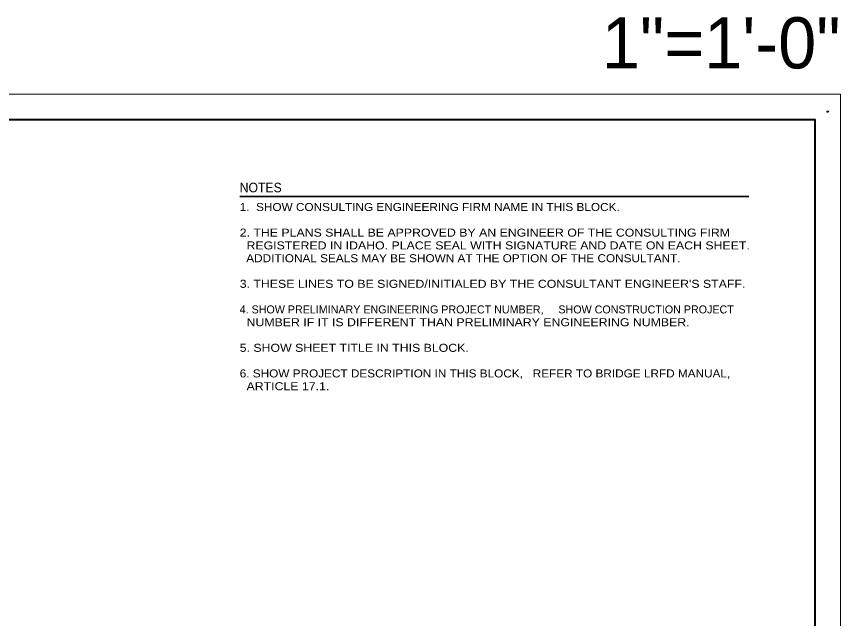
# Model space of a CAD drawing. Extents: x 0 to 34, y 0 to 23.5.
# Drawn here: x 17.91 to 34, y 11.76 to 23.51 of the extents above; entities that cross this region are included whole.
import ezdxf
from ezdxf.enums import TextEntityAlignment as Align

# ---------------------------------------------------------------- set-up
doc = ezdxf.new("R2010")
doc.units = 0
doc.header["$LTSCALE"] = 0.05
doc.header["$PDMODE"] = 32
doc.header["$PDSIZE"] = 0.025
doc.layers.add('49', color=7, linetype='Continuous')
doc.layers.add('50', color=7, linetype='Continuous', lineweight=13)
doc.layers.add('54', color=7, linetype='Continuous', lineweight=25)

msp = doc.modelspace()

# ---------------------------------------------------------------- linework, layer by layer
at = {"layer": '49'}
msp.add_point((33.75, 21.65625), dxfattribs=at)
at = {"layer": '50'}
msp.add_lwpolyline([(0, 22), (34, 22), (34, 0), (0, 0)], close=True, dxfattribs=at)
at = {"layer": '50', "lineweight": 40}
msp.add_lwpolyline([(1.5, 21.5), (33.5, 21.5), (33.5, 0.5), (1.5, 0.5)], close=True, dxfattribs=at)
at = {"layer": '54', "lineweight": 35}
msp.add_line((22.26536, 19.99708), (32.20615, 19.99708), dxfattribs=at)

# ---------------------------------------------------------------- texts
at = {"layer": '50'}
msp.add_text('1"=1\'-0"', height=1, dxfattribs=at).set_placement((34.00068, 22.5), align=Align.RIGHT)
at = {"layer": '54'}
for s, height, width, p in [('NOTES', 0.1875, 0.95, (22.26536, 20.08042)), ('1.  SHOW CONSULTING ENGINEERING FIRM NAME IN THIS BLOCK.', 0.1563, 1.1, (22.26536, 19.71583)), ('2. THE PLANS SHALL BE APPROVED BY AN ENGINEER OF THE CONSULTING FIRM', 0.1563, 1.15, (22.26536, 19.21583)), ('  REGISTERED IN IDAHO. PLACE SEAL WITH SIGNATURE AND DATE ON EACH SHEET.', 0.1563, 1.15, (22.26536, 18.96583)), ('  ADDITIONAL SEALS MAY BE SHOWN AT THE OPTION OF THE CONSULTANT.', 0.1563, 1.1, (22.26536, 18.71583)), ("3. THESE LINES TO BE SIGNED/INITIALED BY THE CONSULTANT ENGINEER'S STAFF.", 0.1563, 1.15, (22.26536, 18.21583)), ('  NUMBER IF IT IS DIFFERENT THAN PRELIMINARY ENGINEERING NUMBER.', 0.1563, 1.15, (22.26536, 17.46583)), ('5. SHOW SHEET TITLE IN THIS BLOCK.', 0.1563, 1.15, (22.26536, 16.96583)), ('6. SHOW PROJECT DESCRIPTION IN THIS BLOCK,   REFER TO BRIDGE LRFD MANUAL,', 0.1563, 1.1, (22.26536, 16.46583)), ('  ARTICLE 17.1.', 0.1563, 1.15, (22.26536, 16.21583))]:
    msp.add_text(s, height=height, dxfattribs=dict(at, width=width)).set_placement(p)
msp.add_text('4. SHOW PRELIMINARY ENGINEERING PROJECT NUMBER,     SHOW CONSTRUCTION PROJECT', height=0.1563, dxfattribs=at).set_placement((22.26536, 17.71583))

doc.saveas('drawing.dxf')
